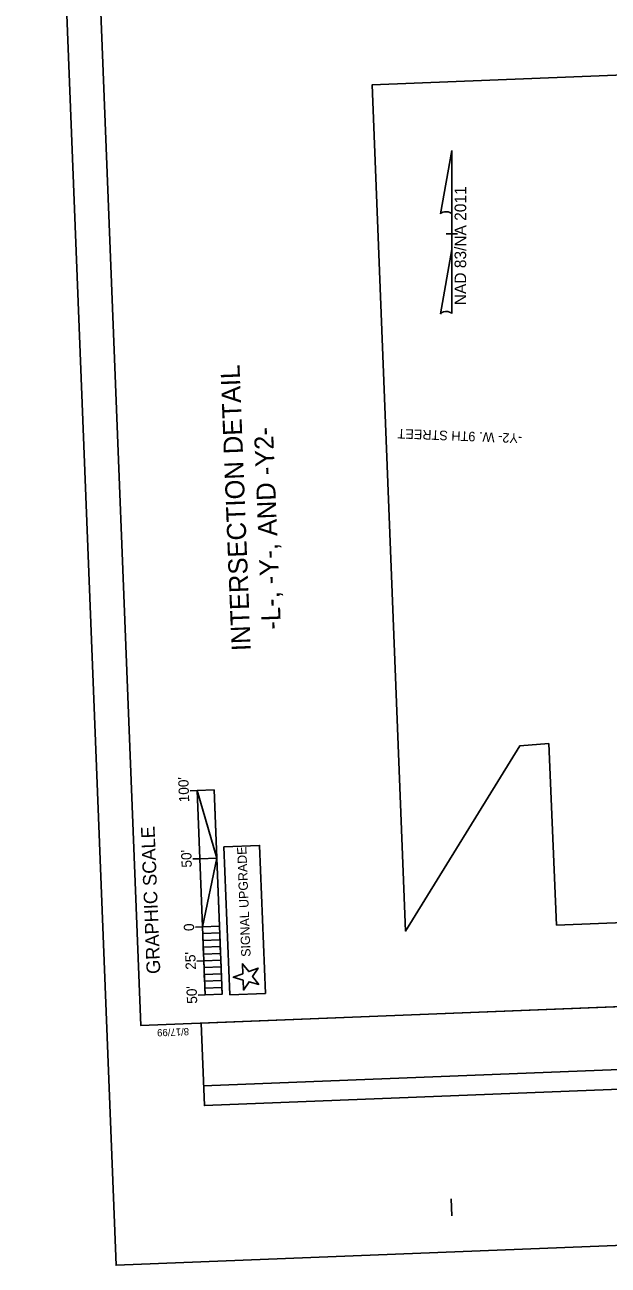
# Model space of a CAD drawing. Extents: x 1627847 to 1629013, y 761524 to 763498.
# Drawn here: x 1627847 to 1628275, y 761524 to 762434 of the extents above; entities that cross this region are included whole.
import ezdxf

# ---------------------------------------------------------------- set-up
doc = ezdxf.new("R2010")
doc.units = 0
for name, color, linetype in [('Prop Dimension', 7, 'Continuous'), ('Prop DSN Text', 7, 'Continuous'), ('Prop Grid Mask', 7, 'Continuous'), ('Prop North Arrow NAD83 for Plan Sheets CELL', 7, 'Continuous'), ('Prop RDY Traffic Signal CELL', 7, 'Continuous'), ('Sheet Block Revision CELL', 7, 'Continuous'), ('Sheet Clip Boundary CELL', 7, 'Continuous'), ('Sheet Data Field CELL', 7, 'Continuous'), ('Sheet Plan And Profile CELL', 7, 'Continuous'), ('Sheet Plot Border Outside CELL', 7, 'Continuous'), ('Sheet Title CELL', 7, 'Continuous')]:
    doc.layers.add(name, color=color, linetype=linetype)

msp = doc.modelspace()

# ---------------------------------------------------------------- linework, layer by layer
at = {"layer": 'Prop Grid Mask'}
msp.add_lwpolyline([(1627997.51, 761722.18), (1627993.23, 761830.78), (1628019.48, 761831.81), (1628023.76, 761723.22)], close=True, dxfattribs=at)
at = {"layer": 'Prop North Arrow NAD83 for Plan Sheets CELL'}
for p, q in [((1628152.25, 762295.23), (1628160.46, 762341.56)), ((1628160.51, 762341.56), (1628160.46, 762341.56)), ((1628160.51, 762341.56), (1628160.46, 762341.56)), ((1628160.51, 762341.56), (1628160.49, 762293.77)), ((1628160.48, 762268.98), (1628160.49, 762295.17)), ((1628160.49, 762293.77), (1628160.49, 762295.12)), ((1628156.49, 762280.58), (1628156.44, 762280.58)), ((1628160.04, 762280.58), (1628156.49, 762280.58)), ((1628156.54, 762280.58), (1628164.54, 762280.57)), ((1628160.48, 762268.98), (1628152.11, 762221.75)), ((1628160.51, 762221.94), (1628160.48, 762268.98))]:
    msp.add_line(p, q, dxfattribs=at)
for centre, start_param, end_param in [((1628156.38, 762294.73), 0.216388, 2.908219), ((1628156.35, 762221.58), 0.201328, 3.141593)]:
    msp.add_ellipse(centre, major_axis=(4.23, -0.03), ratio=0.461098, start_param=start_param, end_param=end_param, dxfattribs=at)
at = {"layer": 'Prop RDY Traffic Signal CELL'}
msp.add_lwpolyline([(1628007.32, 761733.05), (1628007.62, 761725.65), (1628011.73, 761731.81), (1628018.87, 761729.8), (1628014.27, 761735.63), (1628018.39, 761741.79), (1628011.44, 761739.22), (1628006.85, 761745.04), (1628007.14, 761737.64), (1628000.18, 761735.06), (1628007.32, 761733.05)], dxfattribs=at)
at = {"layer": 'Sheet Block Revision CELL'}
msp.add_line((1628768.45, 761686.66), (1627978.41, 761655.51), dxfattribs=at)
msp.add_lwpolyline([(1628769.02, 761672.13), (1627978.99, 761640.97), (1627976.6, 761701.47), (1628766.64, 761732.63)], close=True, dxfattribs=at)
at = {"layer": 'Sheet Clip Boundary CELL'}
msp.add_lwpolyline([(1628237.36, 761773.38), (1628231.63, 761906.6), (1628210.36, 761904.81), (1628126.56, 761769.01), (1628102.08, 762389.86), (1628829.52, 762418.55), (1628854, 761797.69)], close=True, dxfattribs=at)
at = {"layer": 'Sheet Data Field CELL'}
for p, q in [((1627973.56, 761872.05), (1627968.55, 761871.85)), ((1627975.52, 761822.1), (1627970.54, 761821.91)), ((1627978.49, 761747.19), (1627973.5, 761746.99)), ((1627979.47, 761722.21), (1627974.49, 761722.01))]:
    msp.add_line(p, q, dxfattribs=at)
at = {"layer": 'Sheet Plan And Profile CELL'}
msp.add_line((1628160.46, 761560.11), (1628159.97, 761572.6), dxfattribs=at)
msp.add_lwpolyline([(1627873.18, 763198.56), (1627932.28, 761699.73), (1628981.47, 761741.1), (1628922.36, 763239.94)], close=True, dxfattribs=at)
at = {"layer": 'Sheet Plot Border Outside CELL'}
msp.add_lwpolyline([(1629013.34, 761567.22), (1628946.36, 763265.9), (1627847.21, 763222.56), (1627914.2, 761523.88)], close=True, dxfattribs=at)
at = {"layer": 'Sheet Title CELL'}
for p, q in [((1627973.56, 761872.04), (1627968.57, 761871.84)), ((1627986.06, 761872.53), (1627973.56, 761872.04)), ((1627973.56, 761872.04), (1627979.48, 761722.2)), ((1627991.97, 761722.69), (1627986.06, 761872.53)), ((1627975.53, 761822.09), (1627970.55, 761821.9)), ((1627975.53, 761822.09), (1627988.02, 761822.59)), ((1627977.52, 761772.15), (1627972.53, 761771.95)), ((1627978.1, 761757.16), (1627990.59, 761757.66)), ((1627978.51, 761747.17), (1627973.5, 761746.98)), ((1627979.48, 761722.2), (1627974.5, 761722)), ((1627974.5, 761722), (1627974.5, 761722)), ((1627979.48, 761722.2), (1627991.97, 761722.69)), ((1627979.48, 761722.2), (1627979.48, 761722.2))]:
    msp.add_line(p, q, dxfattribs=at)
for points in [[(1627973.56, 761872.04), (1627988.02, 761822.59), (1627986.06, 761872.53)], [(1627977.52, 761772.15), (1627988.02, 761822.59), (1627990.01, 761772.64)], [(1627977.9, 761762.16), (1627977.71, 761767.15), (1627990.2, 761767.64), (1627990.39, 761762.65)], [(1627978.31, 761752.17), (1627978.1, 761757.16), (1627990.59, 761757.66), (1627990.78, 761752.66)], [(1627978.7, 761742.18), (1627978.51, 761747.17), (1627990.98, 761747.67), (1627991.18, 761742.67)], [(1627979.09, 761732.19), (1627978.9, 761737.18), (1627991.39, 761737.68), (1627991.59, 761732.7)], [(1627979.48, 761722.2), (1627979.28, 761727.19), (1627991.77, 761727.69), (1627991.97, 761722.69)]]:
    msp.add_lwpolyline(points, close=True, dxfattribs=at)

# ---------------------------------------------------------------- texts
at = {"layer": 'Prop Dimension'}
for s, p in [('INTERSECTION DETAIL', (1628012.97, 761974.71)), ('-L-, -Y-, AND -Y2-', (1628035.12, 761990.36))]:
    msp.add_text(s, height=14, rotation=92.25819, dxfattribs=at).set_placement(p)
at = {"layer": 'Prop DSN Text'}
for s, height, rotation, p in [('-Y2- W. 9TH STREET', 7, 177.73542, (1628212.25, 762133.82)), ('SIGNAL UPGRADE', 6.8051, 92.25819, (1628012.88, 761750.25))]:
    msp.add_text(s, height=height, rotation=rotation, dxfattribs=at).set_placement(p)
at = {"layer": 'Prop North Arrow NAD83 for Plan Sheets CELL'}
msp.add_text('NAD 83/NA 2011', height=8.4975, rotation=89.97566, dxfattribs=at).set_placement((1628170.98, 762228.16))
at = {"layer": 'Sheet Data Field CELL'}
for s, p in [("100'", (1627967.88, 761863.59)), ("50'", (1627969.78, 761815.71)), ("25'", (1627972.74, 761740.79)), ("50'", (1627973.73, 761715.82))]:
    msp.add_text(s, height=7.498, rotation=92.26296, dxfattribs=at).set_placement(p)
at = {"layer": 'Sheet Plan And Profile CELL'}
msp.add_text('8/17/99', height=5.25, rotation=182.25819, dxfattribs=at).set_placement((1627967.58, 761697.87))
at = {"layer": 'Sheet Title CELL'}
for s, height, p in [('GRAPHIC SCALE', 9.9967, (1627946.65, 761737.72)), ('0', 7.5, (1627971.49, 761769.16))]:
    msp.add_text(s, height=height, rotation=92.26296, dxfattribs=at).set_placement(p)

doc.saveas('drawing.dxf')
